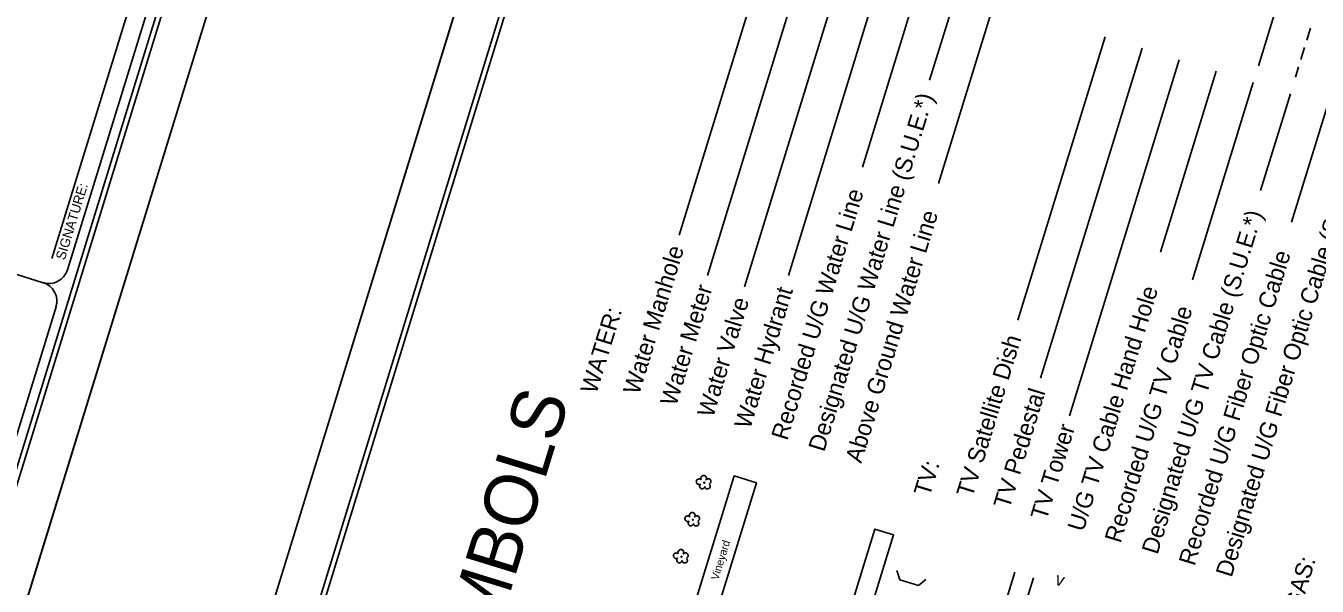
# Model space of a CAD drawing. Extents: x 1347947 to 1350662, y 1027710 to 1030532.
# Drawn here: x 1349324 to 1349990, y 1029300 to 1029589 of the extents above; entities that cross this region are included whole.
import ezdxf

# ---------------------------------------------------------------- set-up
doc = ezdxf.new("R2010")
doc.units = 0
for name, color, linetype in [('Sheet Cutting Line CELL', 7, 'Continuous'), ('Sheet Plot Border Inside CELL', 7, 'Continuous'), ('Sheet Plot Border Outside CELL', 7, 'Continuous'), ('Sheet Symbology CELL', 7, 'Continuous'), ('Sheet Title CELL', 7, 'Continuous')]:
    doc.layers.add(name, color=color, linetype=linetype)

msp = doc.modelspace()

# ---------------------------------------------------------------- linework, layer by layer
at = {"layer": 'Sheet Cutting Line CELL'}
msp.add_line((1348998.14, 1028234.22), (1349493.77, 1029843.63), dxfattribs=at)
at = {"layer": 'Sheet Plot Border Inside CELL'}
msp.add_lwpolyline([(1348980.53, 1028253.25), (1349471, 1029845.94), (1348462.64, 1030156.47), (1347972.16, 1028563.78)], close=True, dxfattribs=at)
at = {"layer": 'Sheet Plot Border Outside CELL'}
msp.add_lwpolyline([(1348442.51, 1030167.38), (1347946.88, 1028557.97), (1348998.14, 1028234.22), (1349493.77, 1029843.63)], close=True, dxfattribs=at)
at = {"layer": 'Sheet Symbology CELL'}
for p, q in [((1349610.32, 1029807.71), (1349114.69, 1028198.29)), ((1349708.85, 1029636.67), (1349661.06, 1029481.47)), ((1349727.96, 1029630.78), (1349675.56, 1029460.63)), ((1349747.08, 1029624.9), (1349694.68, 1029454.75)), ((1349766.19, 1029619.01), (1349717.4, 1029460.57)), ((1349785.31, 1029613.12), (1349755.55, 1029516.49)), ((1349804.42, 1029607.24), (1349790.29, 1029561.35)), ((1349823.53, 1029601.35), (1349794.78, 1029507.97)), ((1349959.99, 1029568.76), (1349970.93, 1029604.29)), ((1349985.01, 1029582.06), (1349986.92, 1029588.27)), ((1349880.88, 1029583.69), (1349835.89, 1029437.61)), ((1349899.99, 1029577.81), (1349847.59, 1029407.65)), ((1349981.92, 1029572.03), (1349983.83, 1029578.24)), ((1349919.11, 1029571.92), (1349862.5, 1029388.1)), ((1349979.1, 1029562.87), (1349980.74, 1029568.2)), ((1349938.22, 1029566.03), (1349909.46, 1029472.65)), ((1349957.33, 1029560.15), (1349925.97, 1029458.3)), ((1349976.45, 1029554.26), (1349961.11, 1029504.47)), ((1349995.56, 1029548.37), (1349977.02, 1029488.18)), ((1349773.37, 1029308.26), (1349774.9, 1029303.5)), ((1349809.98, 1029228.61), (1349834.26, 1029307.45)), ((1349774.9, 1029303.5), (1349784.46, 1029300.56)), ((1349788.4, 1029303.63), (1349784.46, 1029300.56)), ((1349819.54, 1029225.66), (1349843.82, 1029304.51))]:
    msp.add_line(p, q, dxfattribs=at)
for points in [[(1350165.97, 1027874.54), (1350661.6, 1029483.96), (1349610.32, 1029807.71), (1349114.69, 1028198.29)], [(1350148.34, 1027893.58), (1350638.82, 1029486.26), (1349630.46, 1029796.8), (1349139.98, 1028204.11)], [(1349629.21, 1029784.1), (1349187.74, 1028350.54), (1350190.26, 1028041.81), (1350631.74, 1029475.37)]]:
    msp.add_lwpolyline(points, close=True, dxfattribs=at)
for points in [[(1349665.9, 1029280.73), (1349689.45, 1029357.18), (1349700.92, 1029353.65), (1349677.37, 1029277.19), (1349665.9, 1029280.73)], [(1349672.35, 1029355.18), (1349672.11, 1029355.41), (1349671.84, 1029355.54), (1349671.54, 1029355.58), (1349671.23, 1029355.63), (1349670.95, 1029355.56), (1349670.67, 1029355.49), (1349670.4, 1029355.31), (1349670.19, 1029355.11), (1349669.99, 1029354.81), (1349669.92, 1029354.57), (1349669.87, 1029354.27), (1349669.88, 1029353.95), (1349669.95, 1029353.67), (1349670.07, 1029353.37), (1349670.31, 1029353.14), (1349670.52, 1029352.97), (1349670.79, 1029352.83), (1349671.08, 1029352.74), (1349671.38, 1029352.7), (1349671.66, 1029352.77), (1349672.01, 1029352.88), (1349671.79, 1029352.68), (1349671.66, 1029352.41), (1349671.57, 1029352.12), (1349671.59, 1029351.85), (1349671.61, 1029351.59), (1349671.73, 1029351.29), (1349671.86, 1029351.04), (1349672.06, 1029350.82), (1349672.28, 1029350.7), (1349672.6, 1029350.55), (1349672.85, 1029350.52), (1349673.12, 1029350.54), (1349673.42, 1029350.66), (1349673.66, 1029350.75), (1349673.87, 1029350.94), (1349674.1, 1029351.18), (1349674.23, 1029351.41), (1349674.31, 1029351.69), (1349674.34, 1029351.43), (1349674.45, 1029351.13), (1349674.6, 1029350.93), (1349674.86, 1029350.74), (1349675.12, 1029350.56), (1349675.35, 1029350.49), (1349675.66, 1029350.44), (1349675.94, 1029350.51), (1349676.22, 1029350.58), (1349676.47, 1029350.72), (1349676.69, 1029350.91), (1349676.86, 1029351.12), (1349676.95, 1029351.41), (1349677.03, 1029351.69), (1349677.06, 1029351.95), (1349676.94, 1029352.25), (1349676.87, 1029352.53), (1349676.52, 1029352.9)], [(1349676.52, 1029352.9), (1349677.03, 1029353.37), (1349677.21, 1029353.63), (1349677.35, 1029353.9), (1349677.39, 1029354.2), (1349677.37, 1029354.47), (1349677.3, 1029354.75), (1349677.18, 1029355.05), (1349676.98, 1029355.27), (1349676.77, 1029355.44), (1349676.52, 1029355.62), (1349676.22, 1029355.66), (1349675.91, 1029355.7), (1349675.57, 1029355.6), (1349675.33, 1029355.51), (1349675.12, 1029355.32), (1349674.89, 1029355.08), (1349675.02, 1029355.35), (1349675.12, 1029355.68), (1349675.1, 1029355.95), (1349675.05, 1029356.28), (1349674.98, 1029356.57), (1349674.8, 1029356.83), (1349674.55, 1029357.06), (1349674.28, 1029357.2), (1349674.01, 1029357.33), (1349673.71, 1029357.37), (1349673.39, 1029357.37), (1349673.1, 1029357.25), (1349672.78, 1029357.08), (1349672.57, 1029356.89), (1349672.38, 1029356.63), (1349672.25, 1029356.36), (1349672.16, 1029356.07), (1349672.17, 1029355.76), (1349672.23, 1029355.47), (1349672.35, 1029355.18)], [(1349673.77, 1029353.85), (1349673.73, 1029353.71), (1349673.75, 1029353.6), (1349673.77, 1029353.49), (1349673.91, 1029353.44), (1349674.01, 1029353.41), (1349674.13, 1029353.48), (1349674.18, 1029353.62), (1349674.2, 1029353.72), (1349674.14, 1029353.84), (1349674.01, 1029353.93), (1349673.9, 1029353.92), (1349673.77, 1029353.85)], [(1349666.47, 1029336.06), (1349666.22, 1029336.29), (1349665.95, 1029336.43), (1349665.65, 1029336.47), (1349665.35, 1029336.51), (1349665.07, 1029336.44), (1349664.78, 1029336.37), (1349664.52, 1029336.19), (1349664.3, 1029336), (1349664.1, 1029335.69), (1349664.03, 1029335.45), (1349663.99, 1029335.15), (1349664, 1029334.84), (1349664.07, 1029334.55), (1349664.18, 1029334.25), (1349664.43, 1029334.02), (1349664.63, 1029333.85), (1349664.91, 1029333.72), (1349665.19, 1029333.63), (1349665.49, 1029333.59), (1349665.78, 1029333.66), (1349666.12, 1029333.76), (1349665.91, 1029333.57), (1349665.77, 1029333.29), (1349665.68, 1029333.01), (1349665.7, 1029332.74), (1349665.73, 1029332.47), (1349665.84, 1029332.17), (1349665.98, 1029331.92), (1349666.17, 1029331.71), (1349666.4, 1029331.59), (1349666.71, 1029331.43), (1349666.97, 1029331.41), (1349667.24, 1029331.43), (1349667.53, 1029331.55), (1349667.77, 1029331.63), (1349667.99, 1029331.83), (1349668.22, 1029332.07), (1349668.34, 1029332.29), (1349668.43, 1029332.58), (1349668.45, 1029332.31), (1349668.57, 1029332.01), (1349668.71, 1029331.81), (1349668.97, 1029331.63), (1349669.23, 1029331.44), (1349669.47, 1029331.37), (1349669.77, 1029331.33), (1349670.05, 1029331.4), (1349670.34, 1029331.47), (1349670.59, 1029331.6), (1349670.8, 1029331.8), (1349670.97, 1029332.01), (1349671.06, 1029332.29), (1349671.15, 1029332.58), (1349671.17, 1029332.83), (1349671.06, 1029333.13), (1349670.99, 1029333.41), (1349670.63, 1029333.79)], [(1349670.63, 1029333.79), (1349671.14, 1029334.26), (1349671.33, 1029334.51), (1349671.46, 1029334.79), (1349671.5, 1029335.09), (1349671.48, 1029335.36), (1349671.41, 1029335.64), (1349671.29, 1029335.94), (1349671.1, 1029336.15), (1349670.89, 1029336.32), (1349670.63, 1029336.51), (1349670.33, 1029336.55), (1349670.03, 1029336.59), (1349669.68, 1029336.48), (1349669.45, 1029336.4), (1349669.23, 1029336.21), (1349669, 1029335.96), (1349669.13, 1029336.23), (1349669.24, 1029336.57), (1349669.22, 1029336.84), (1349669.16, 1029337.17), (1349669.09, 1029337.45), (1349668.91, 1029337.72), (1349668.67, 1029337.95), (1349668.4, 1029338.08), (1349668.12, 1029338.22), (1349667.82, 1029338.26), (1349667.51, 1029338.25), (1349667.21, 1029338.14), (1349666.9, 1029337.97), (1349666.68, 1029337.78), (1349666.5, 1029337.52), (1349666.36, 1029337.25), (1349666.27, 1029336.96), (1349666.28, 1029336.64), (1349666.35, 1029336.36), (1349666.47, 1029336.06)], [(1349667.89, 1029334.74), (1349667.84, 1029334.59), (1349667.86, 1029334.48), (1349667.88, 1029334.37), (1349668.02, 1029334.33), (1349668.12, 1029334.3), (1349668.24, 1029334.36), (1349668.29, 1029334.51), (1349668.32, 1029334.6), (1349668.25, 1029334.73), (1349668.12, 1029334.82), (1349668.01, 1029334.8), (1349667.89, 1029334.74)], [(1349737.76, 1029250.85), (1349762.04, 1029329.69), (1349771.6, 1029326.75), (1349747.31, 1029247.9), (1349737.76, 1029250.85)], [(1349660.58, 1029316.95), (1349660.34, 1029317.18), (1349660.07, 1029317.32), (1349659.76, 1029317.36), (1349659.46, 1029317.4), (1349659.18, 1029317.33), (1349658.9, 1029317.26), (1349658.63, 1029317.08), (1349658.41, 1029316.88), (1349658.22, 1029316.58), (1349658.14, 1029316.34), (1349658.1, 1029316.04), (1349658.11, 1029315.72), (1349658.18, 1029315.44), (1349658.3, 1029315.14), (1349658.54, 1029314.91), (1349658.75, 1029314.74), (1349659.02, 1029314.6), (1349659.31, 1029314.52), (1349659.61, 1029314.47), (1349659.89, 1029314.54), (1349660.24, 1029314.65), (1349660.02, 1029314.45), (1349659.88, 1029314.18), (1349659.8, 1029313.89), (1349659.82, 1029313.63), (1349659.84, 1029313.36), (1349659.96, 1029313.06), (1349660.09, 1029312.81), (1349660.28, 1029312.59), (1349660.51, 1029312.47), (1349660.83, 1029312.32), (1349661.08, 1029312.29), (1349661.35, 1029312.32), (1349661.65, 1029312.43), (1349661.88, 1029312.52), (1349662.1, 1029312.71), (1349662.33, 1029312.96), (1349662.45, 1029313.18), (1349662.54, 1029313.47), (1349662.56, 1029313.2), (1349662.68, 1029312.9), (1349662.83, 1029312.7), (1349663.09, 1029312.51), (1349663.34, 1029312.33), (1349663.58, 1029312.26), (1349663.88, 1029312.22), (1349664.17, 1029312.29), (1349664.45, 1029312.36), (1349664.7, 1029312.49), (1349664.92, 1029312.68), (1349665.09, 1029312.89), (1349665.17, 1029313.18), (1349665.26, 1029313.47), (1349665.29, 1029313.72), (1349665.17, 1029314.02), (1349665.1, 1029314.3), (1349664.74, 1029314.67)], [(1349664.74, 1029314.67), (1349665.26, 1029315.14), (1349665.44, 1029315.4), (1349665.58, 1029315.67), (1349665.62, 1029315.97), (1349665.59, 1029316.24), (1349665.52, 1029316.52), (1349665.41, 1029316.82), (1349665.21, 1029317.04), (1349665, 1029317.21), (1349664.74, 1029317.39), (1349664.44, 1029317.43), (1349664.14, 1029317.47), (1349663.8, 1029317.37), (1349663.56, 1029317.29), (1349663.34, 1029317.09), (1349663.11, 1029316.85), (1349663.25, 1029317.12), (1349663.35, 1029317.45), (1349663.33, 1029317.72), (1349663.27, 1029318.05), (1349663.2, 1029318.34), (1349663.02, 1029318.6), (1349662.78, 1029318.83), (1349662.51, 1029318.97), (1349662.24, 1029319.11), (1349661.94, 1029319.15), (1349661.62, 1029319.14), (1349661.32, 1029319.02), (1349661.01, 1029318.86), (1349660.79, 1029318.66), (1349660.61, 1029318.4), (1349660.47, 1029318.13), (1349660.39, 1029317.85), (1349660.39, 1029317.53), (1349660.46, 1029317.25), (1349660.58, 1029316.95)], [(1349662, 1029315.62), (1349661.96, 1029315.48), (1349661.98, 1029315.37), (1349661.99, 1029315.26), (1349662.14, 1029315.21), (1349662.23, 1029315.18), (1349662.36, 1029315.25), (1349662.4, 1029315.39), (1349662.43, 1029315.49), (1349662.37, 1029315.61), (1349662.24, 1029315.71), (1349662.13, 1029315.69), (1349662, 1029315.62)]]:
    msp.add_lwpolyline(points, dxfattribs=at)
at = {"layer": 'Sheet Title CELL'}
for p, q in [((1349337.24, 1029469.38), (1349378.9, 1029604.61)), ((1349332.83, 1029456.87), (1349179.91, 1029503.96))]:
    msp.add_line(p, q, dxfattribs=at)
for points in [[(1349026.36, 1028410.74), (1349461.95, 1029825.18)], [(1349345.31, 1029463.49), (1349404.11, 1029654.42)], [(1349255.55, 1029172), (1349339.44, 1029444.37)]]:
    msp.add_lwpolyline(points, dxfattribs=at)
for centre, start, end in [((1349335.72, 1029466.45), 252.88342, 342.88342), ((1349329.83, 1029447.34), 342.88342, 72.88342)]:
    msp.add_arc(centre, 10, start, end, dxfattribs=at)

# ---------------------------------------------------------------- texts
at = {"layer": 'Sheet Symbology CELL'}
for s, height, rotation, p in [('Designated U/G Water Line (S.U.E.*)', 8.75, 72.88342, (1349735.85, 1029369.17)), ('Designated U/G Fiber Optic Cable (S.U.E.*)', 8.75, 72.88342, (1349946.11, 1029304.42)), ('Recorded U/G Water Line', 8.75, 72.88342, (1349716.74, 1029375.06)), ('Above Ground Water Line', 8.75, 72.88342, (1349754.97, 1029363.29)), ('Designated U/G TV Cable (S.U.E.*)', 8.75, 72.88342, (1349907.88, 1029316.2)), ('Water Manhole', 8.75, 72.88342, (1349640.28, 1029398.61)), ('Recorded U/G Fiber Optic Cable', 8.75, 72.88342, (1349927, 1029310.31)), ('Water Meter', 8.75, 72.88342, (1349659.4, 1029392.72)), ('Water Hydrant', 8.75, 72.88342, (1349697.63, 1029380.95)), ('U/G TV Cable Hand Hole', 8.75, 72.88342, (1349869.65, 1029327.97)), ('Water Valve', 8.75, 72.88342, (1349678.51, 1029386.83)), ('WATER:', 8.75, 72.88342, (1349618.24, 1029399.06)), ('Recorded U/G TV Cable', 8.75, 72.88342, (1349888.77, 1029322.08)), ('TV Satellite Dish', 8.75, 72.88342, (1349812.31, 1029345.63)), ('CONVENTIONAL  PLAN SHEET SYMBOLS', 27.2003, 72.88342, (1349392.79, 1028709.05)), ('TV Pedestal', 8.75, 72.88342, (1349831.43, 1029339.74)), ('TV Tower', 8.75, 72.88342, (1349850.54, 1029333.86)), ('TV:', 8.75, 72.88342, (1349790.27, 1029346.09)), ('Vineyard', 4, 72.88344, (1349681.15, 1029303.05)), ('GAS:', 8.75, 72.88342, (1349981.41, 1029287.22)), ('v', 6.6, 343.12427, (1349854.58, 1029301.18))]:
    msp.add_text(s, height=height, rotation=rotation, dxfattribs=at).set_placement(p)
at = {"layer": 'Sheet Title CELL'}
msp.add_text('SIGNATURE:', height=5, rotation=72.88342, dxfattribs=at).set_placement((1349343.91, 1029468.27))

doc.saveas('drawing.dxf')
